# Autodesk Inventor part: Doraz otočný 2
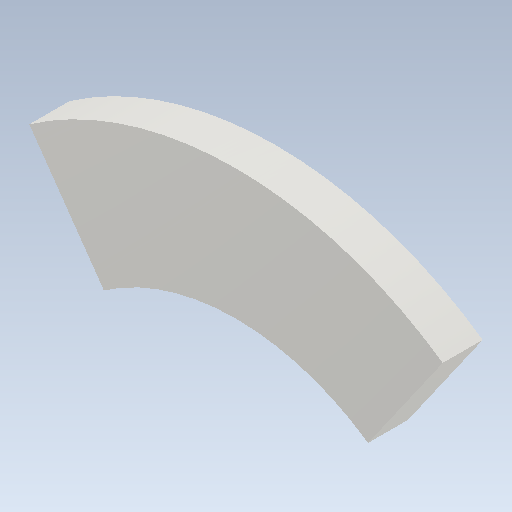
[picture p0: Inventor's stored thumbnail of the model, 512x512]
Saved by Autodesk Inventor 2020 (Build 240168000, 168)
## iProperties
Created: 2025-03
Part Number: Doraz otočný 2
Material: Ocel
Document SubType Name: Modeling
Designer: doma
Density: 7.85 g/cm^3
Appearance: Ocel
Mass: 229.874 g
Surface Area: 83.0872 cm^2
Volume: 29.2834 cm^3
Author: doma
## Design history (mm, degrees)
sketch "Náčrt1"
  geometry: L1 (0, 0)-(51.622, 73.724); L2 (0, 0)-(-51.622, 73.724); L3 (-51.622, 73.724)-(51.622, 73.724); C1 r 57.5 at (0, 0); A1 r 90 centre (0, 0) between (51.622, 73.724) and (-51.622, 73.724); 3 further points
  constraints: 6 end point, 2 centre point, 2 coincident, 2 point on circle, 1 horizontal
  dimensions: "d0" = 115 diameter of C1; "d1" = 180 diameter of A1; "d2" = 70 deg angle of L1 L2
extrude "Vysunutí1" new body sketch "Náčrt1" distance "d3" = 10; taper "d4" = 0 deg
node "Těleso1"
